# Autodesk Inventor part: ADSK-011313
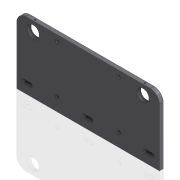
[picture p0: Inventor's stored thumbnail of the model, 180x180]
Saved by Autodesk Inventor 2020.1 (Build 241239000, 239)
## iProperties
Created: 1999-12
Part Number: ADSK-011313
Material: Acier doux
Description: PLT-38,FH,CP,03,150,070,MNT,BEARING
Document SubType Name: Modeling
Designer: sspink
Density: 7.86 g/cm^3
Appearance: Metal-Steel(Polish)
Mass: 5078.55 g
Surface Area: 1456.72 cm^2
Volume: 646.126 cm^3
Control State: 0
Checked Out: False
Last Check In By: sspink
Last Check In Date: 1999-12-22
Master: False
Shininess: 0.0
Length Units: 11269
Angle Units: 11279
Time Units: 11290
Mass Units: 11283
Length Display Precision: 3
Angle Display Precision: 2
Compacted: True
Dimensions: 380x178x10 mm
Mass: 5,079 kg
DocNumber: ADSK-011313.ipt
Folder: 01 - Themengebiete\Simplification\01 - Packaging machine\
VDS_Category: 3D Komponenten
Density: 0.0
Volumn: 0.0
Area: 0.0
PropertySet Name: Model Information
Author: sspink
Revision Number: -
Title: PLT-38,FH,CP,03,150,070,MNT,BEARING
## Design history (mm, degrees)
node "Solide1"
  node "Extrusion1" dims "d4" = 10, "d5" = 0
  node "Fillet3" dims "d38" = 25
  node "Extrusion4" dims "d47" = 25.4, "d48" = 0
  node "Hole2" dims "d57" = 9, "d58" = 19, "d59" = 6.35, "d60" = 90 deg, "d61" = 19.05, "d62" = 118 deg, "d79" = 6
  node "Hole3" dims "d66" = 4.134, "d67" = 20.6375, "d68" = 6.35, "d69" = 60 deg, "d70" = 14.2, "d71" = 118 deg, "d80" = 10
sketch "Sketch1"
  geometry: L1 (-31.855, -279.391)-(348.145, -279.391) reference; L2 (348.145, -279.391)-(348.145, -101.391); L3 (348.145, -101.391)-(-31.855, -101.391); L4 (-31.855, -101.391)-(-31.855, -279.391); L5 (158.145, -279.391)-(158.145, -101.391) reference; C1 r 16 at (304.145, -126.891); C2 r 16 at (12.145, -126.891)
  constraints: 10 end point, 2 centre point, 2 horizontal, 2 midpoint, 2 parallel, 1 equal radius, 1 perpendicular, 1 vertical
  dimensions: "d31" = 380 distance of L1.start L1.end; "d32" = 178 distance of L3.end L1.start; "d33" = 146 distance from line of L5 C2.centre; "d34" = 146 distance from line of C1.centre L5 (= d33); "d35" = 152.5 distance from line of C2.centre L1; "d36" = 152.5 distance from line of C1.centre L1 (= d35); "d37" = 32 diameter of C1
workplane "Arbeitsebene3"
workpoint "Arbeitspunkt1"
workpoint "Arbeitspunkt2"
workpoint "Arbeitspunkt3"
workaxis "Arbeitsachse1"
workaxis "Arbeitsachse2"
workaxis "Arbeitsachse3"
workplane "Work Plane1"
workplane "Work Plane2"
sketch "Sketch5"
  geometry: L1 (348.145, -279.391)-(-31.855, -279.391) reference; L2 (-12.855, -256.891)-(5.145, -256.891); L3 (5.145, -256.891)-(5.145, -247.891); L4 (5.145, -247.891)-(-12.855, -247.891); L5 (-12.855, -247.891)-(-12.855, -256.891); L6 (311.145, -256.891)-(329.145, -256.891); L7 (329.145, -256.891)-(329.145, -247.891); L8 (329.145, -247.891)-(311.145, -247.891); L9 (311.145, -247.891)-(311.145, -256.891); L10 (149.145, -256.891)-(167.145, -256.891); L11 (167.145, -256.891)-(167.145, -247.891); L12 (167.145, -247.891)-(149.145, -247.891); L13 (149.145, -247.891)-(149.145, -256.891); L14 (158.145, -279.391)-(158.145, -256.891); L15 (-12.855, -252.391)-(5.145, -252.391); L16 (149.145, -252.391)-(167.145, -252.391); L17 (311.145, -252.391)-(329.145, -252.391); A1 r 4.5 centre (-12.855, -252.391) between (-12.855, -247.891) and (-12.855, -256.891); A2 r 4.5 centre (311.145, -252.391) between (311.145, -247.891) and (311.145, -256.891); A3 r 4.5 centre (329.145, -252.391) between (329.145, -256.891) and (329.145, -247.891); A4 r 4.5 centre (5.145, -252.391) between (5.145, -256.891) and (5.145, -247.891); A5 r 4.5 centre (149.145, -252.391) between (149.145, -247.891) and (149.145, -256.891); A6 r 4.5 centre (167.145, -252.391) between (167.145, -256.891) and (167.145, -247.891); 2 further points
  constraints: 32 end point, 12 point on circle, 6 centre point, 6 parallel, 6 tangent, 5 horizontal, 5 perpendicular, 4 midpoint, 2 collinear
  dimensions: "d39" = 9 distance of L2.end L3.end; "d40" = 9 distance of L6.end L7.end (= d39); "d41" = 18 distance of L2.start L2.end; "d42" = 18 distance of L6.start L6.end (= d41); "d63" = 9 distance of L12.end L10.start (= d39); "d64" = 18 distance of L10.start L10.end (= d41); "d65" = 27 distance from line of L16.start L1; "d74" = 324 distance of point (320.145, -252.391) point (-3.855, -252.391); "d75" = 162 distance from line of point (320.145, -252.391) L14 (= 0.5 x d74)
sketch "Sketch6"
  geometry: L1 (31.855, -279.391)-(-348.145, -279.391) reference; L2 (-323.145, -101.391)-(6.855, -101.391) reference; L3 (-240.145, -117.391)-(-76.145, -117.391); L4 (-76.145, -117.391)-(-76.145, -244.391); L5 (-76.145, -244.391)-(-240.145, -244.391); L6 (-240.145, -244.391)-(-240.145, -117.391); 4 further points
  constraints: 8 end point, 2 coincident, 2 midpoint, 2 parallel, 1 horizontal, 1 perpendicular, 1 vertical alignment
  dimensions: "d76" = 35 distance between parallel lines of L1 L5; "d77" = 127 distance of L5.end L3.start; "d78" = 164 distance of L3.start L3.end
node "Corps solides"
node "Corps surfaciques"
sketch "Sketch8"
  geometry: L1 (0, -10)-(330, -10) reference; L2 (3.111, 0)-(34.988, 0) reference; L3 (19.05, 0)-(19.05, -10); L4 (295.212, 0)-(327.089, 0) reference; L5 (311.15, 0)-(311.15, -10); 2 further points
  constraints: 4 end point, 4 midpoint, 2 perpendicular, 2 point on line
other parameters: "d72" = -12.7, "d73" = -228.6
